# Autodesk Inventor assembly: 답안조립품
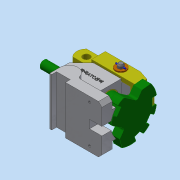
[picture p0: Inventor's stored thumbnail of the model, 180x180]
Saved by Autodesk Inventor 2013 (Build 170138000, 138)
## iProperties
Created: 2016-11
Part Number: 답안조립품
Document SubType Name: Assembly
Designer: dgall
Author: dgall
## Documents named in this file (8)
- C:\Users\dgall\Desktop\461107V1014\답안조립품.iam
- C:\Users\dgall\Desktop\461107V1014\본체.ipt
- C:\Users\dgall\Desktop\461107V1014\부시.ipt
- C:\Users\dgall\Desktop\461107V1014\분할대.ipt
- C:\Users\dgall\Desktop\461107V1014\분할축.ipt
- C:\Users\dgall\Desktop\461107V1014\클레비스핀.ipt
- C:\Users\dgall\Desktop\461107V1014\와셔.ipt
- C:\Users\dgall\Desktop\461107V1014\원통형핀.ipt
